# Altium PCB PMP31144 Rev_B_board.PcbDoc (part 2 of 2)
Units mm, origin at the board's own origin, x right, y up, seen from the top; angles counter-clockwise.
Board outline 104.14 x 73.15 mm, 4 copper layers (Top Layer, Layer 1, Layer 2, Bottom Layer), stack 1.787 mm thick; 110 components, 51 nets, 277 pads, 139 vias.
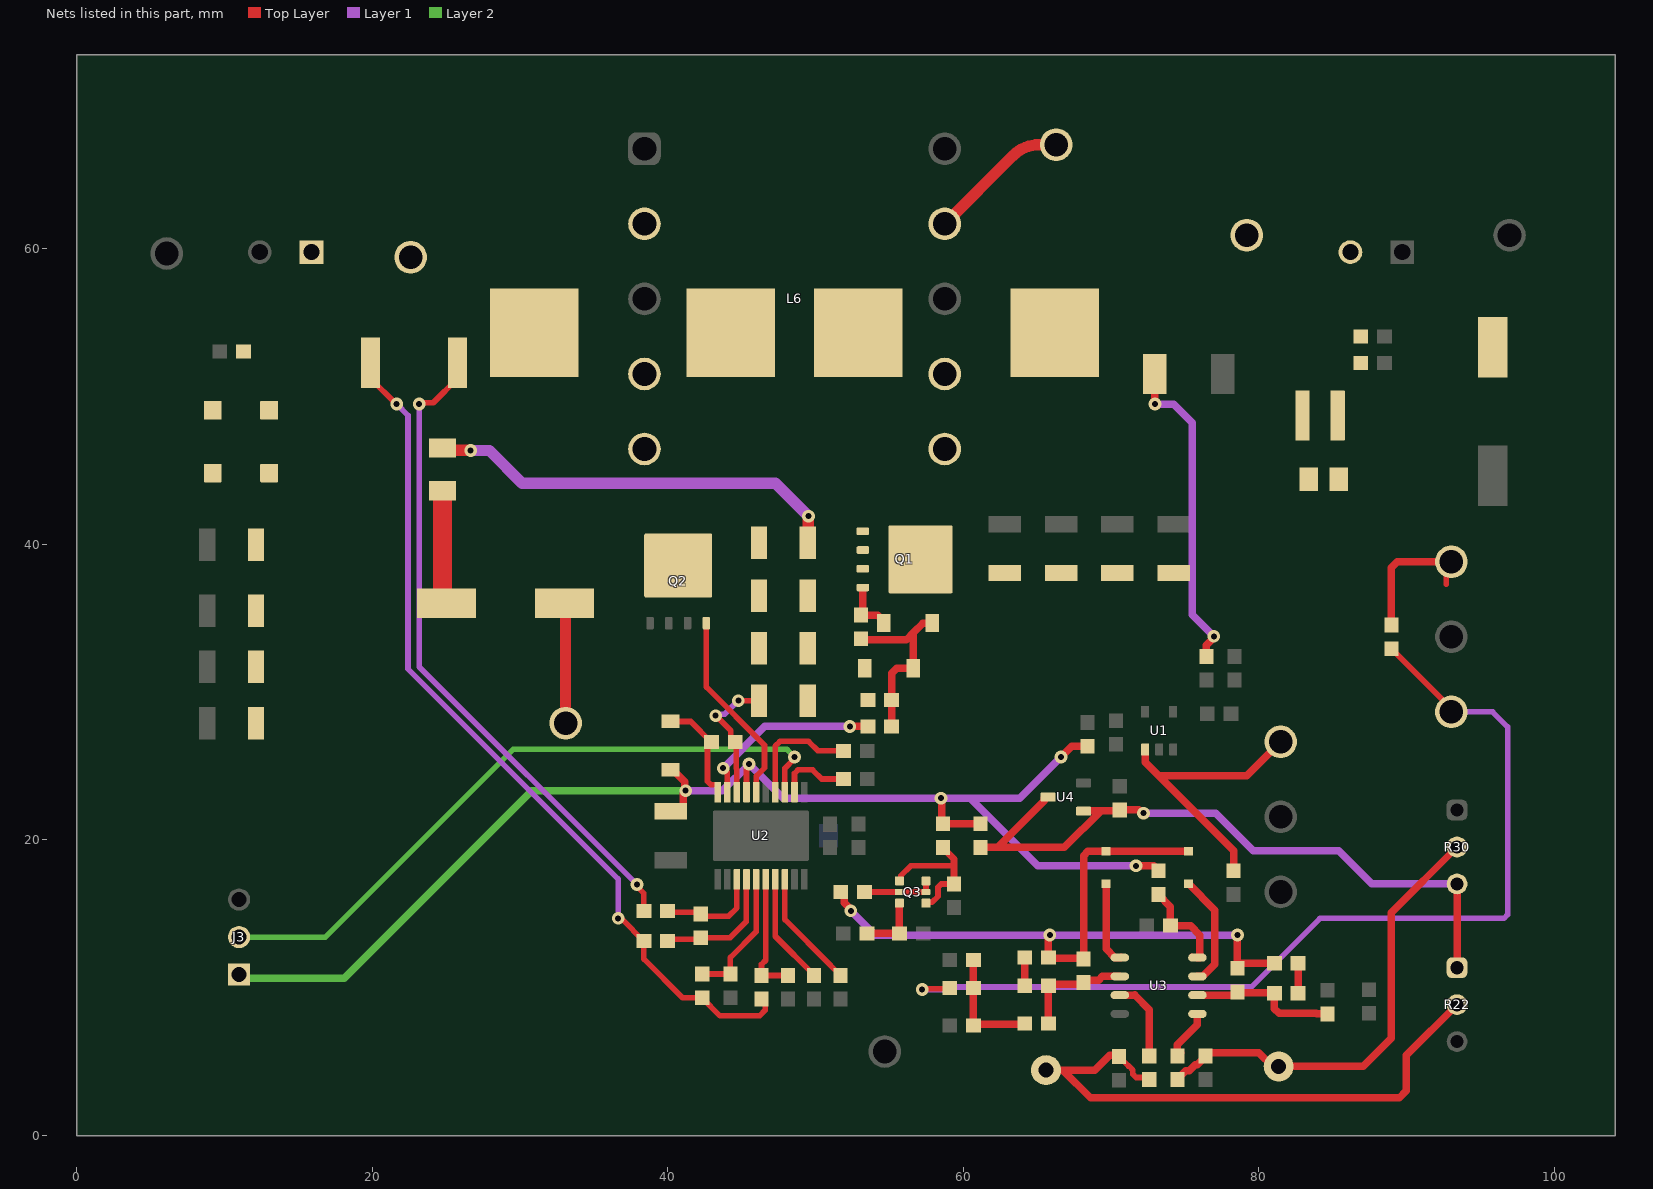
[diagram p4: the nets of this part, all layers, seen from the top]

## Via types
v1: diameter 0.864, hole 0.406, Top Layer to Bottom Layer, 59 vias
v2: diameter 1.016, hole 0.508, Top Layer to Bottom Layer, 39 vias
v3: diameter 1.016, hole 0.508, Top Layer to Bottom Layer, tented top, 15 vias
v4: diameter 0.864, hole 0.406, Top Layer to Bottom Layer, tented top, 11 vias
v5: diameter 0.5, hole 0.2, Top Layer to Bottom Layer, 9 vias
v6: diameter 0.5, hole 0.2, Top Layer to Bottom Layer, tented both sides, 6 vias

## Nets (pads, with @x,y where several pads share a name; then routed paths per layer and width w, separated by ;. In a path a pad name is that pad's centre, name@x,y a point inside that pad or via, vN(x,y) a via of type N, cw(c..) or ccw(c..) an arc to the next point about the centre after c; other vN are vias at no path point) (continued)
NetC3_1: C3.1 C4.1 C5.1 C6.1 D1.2 L1.2 L6.6 L6.9 Q1.1 Q1.2 Q1.3 R6.2 R11.1 TP5.1 | length 38.5
  Top Layer w0.508: C3.1@49.477,29.431 C3.1@49.698,29.21
  Top Layer w0.762: R6.2@24.765,46.535 24.926,46.374 26.651,46.374 v1(26.67,46.355) ; C6.1@49.477,40.099 49.511,40.133 49.511,41.891 v1(49.53,41.91) ; L6.9@58.75,61.697 63.366,66.312 cw(c65.162,64.516) 65.162,67.056 TP5.1@66.294,67.056
  Layer 1 w0.762: v1(26.67,46.355) 27.94,46.355 30.153,44.142 47.298,44.142 v1(49.53,41.91)
NetC3_2: C3.2 C4.2 C5.2 C6.2 C7.1 C21.1 L2.2 L6.4 L6.5 Q2.5 Q2.6 Q2.7 Q2.8 Q2.9@40.715,38.575 TP7.1 U2.18 | length 17.3
  Top Layer w0.381: v1(43.255,28.415) 44.271,27.399 44.271,26.922 44.555,26.637 C21.1@44.571,26.637 44.632,26.576 44.632,24.84 44.686,24.786 U2.18@44.686,23.237 ; v1(44.779,29.431) C3.2@46.177,29.431
  Top Layer w0.762: C7.1@33.031,36.035 33.095,35.971 TP7.1@33.095,27.907
  Layer 1 w0.381: v1(43.255,28.415) 43.347,28.507 43.855,28.507 v1(44.779,29.431)
NetC7_2: C7.2 R6.1 | length 7.7
  Top Layer w1.27: R6.1@24.765,43.635 24.765,36.301 C7.2@25.031,36.035
NetC8_1: C8.1 C9.1 C10.1 C11.1 L4.1 Q1.5 Q1.6 Q1.7 Q1.8 Q1.9@57.113,38.989 R7.1
NetC12_1: C12.1 R9.1 U2.5 | length 9
  Top Layer w0.381: R9.1@42.341,10.927 C12.1@44.246,10.927 44.246,12.05 45.986,13.79 U2.5@45.986,17.337
NetC13_1: C13.1 R13.1 U2.4 | length 8.5
  Top Layer w0.381: R13.1@39.991,13.175 40.099,13.283 42.131,13.283 C13.1@42.239,13.391 44.233,13.391 45.321,14.479 U2.4@45.321,17.077
NetC13_2: C13.2 R14.1 U2.3 | length 7
  Top Layer w0.381: R14.1@39.991,15.207 40.099,15.099 42.131,15.099 C13.2@42.239,14.991 42.391,14.839 44.126,14.839 44.686,15.399 U2.3@44.686,17.337
NetC14_1: C14.1 J1.1 L3.1 L5.1 TP4.1
NetC15_1: C15.1 C37.1 C38.1 J2.2 L4.2 R7.2 R10.1 TP6.1 TP15.1 | length 9.8
  Top Layer w0.381: 92.689,37.31 92.689,38.479 TP6.1@93.039,38.829
  Top Layer w0.508: R10.1@88.975,34.549 88.975,38.429 89.375,38.829 TP6.1@93.039,38.829
NetC16_1: C16.1 C17.1 C18.1 C19.1 L3.2 L5.2 R8.2 R9.2 R12.2 R13.2 | length 58.9
  Top Layer w0.381: R8.2@19.887,52.291 19.887,51.241 21.631,49.497 v1(21.665,49.497) ; v1(36.651,14.699) 36.743,14.607 36.934,14.607 38.366,13.175 R13.2@38.391,13.175 38.391,11.943 41.007,9.327 R9.2@42.341,9.327 42.341,9.302 43.548,8.095 46.221,8.095 46.609,8.483 R12.2@46.609,9.233
  Layer 1 w0.381: v1(21.665,49.497) 22.427,48.735 22.427,31.581 36.651,17.357 v1(36.651,14.699)
NetC20_1: C20.1 D1.1 D100.1 R11.2 R100.1 | length 12.9
  Top Layer w0.5: R100.1@53.086,33.617 53.146,33.557 56.163,33.557 56.628,34.022 ; C20.1@55.156,27.686 R11.2@55.156,29.464 55.156,31.28 55.499,31.623 D1.1@56.628,31.623 56.628,34.022 ; D100.1@57.898,34.671 57.277,34.671 56.628,34.022
NetC20_2: C20.2 U2.19 | length 12.7
  Top Layer w0.381: v4(43.756,24.859) 43.763,24.859 44.036,24.586 U2.19@44.036,23.237
  Top Layer w0.5: v4(52.324,27.686) C20.2@53.556,27.686
  Layer 1 w0.5: v4(43.756,24.859) 46.583,27.686 v4(52.324,27.686)
  Layer 2 w0.381: v4(43.756,24.859) v4@43.763,24.859
NetC21_2: C21.2 D2.1 U2.20 | length 7.4
  Top Layer w0.381: D2.1@40.207,28.021 41.562,28.021 42.946,26.637 C21.2@42.971,26.637 42.696,26.362 42.696,23.97 42.92,23.747 43.351,23.747 43.386,23.712 U2.20@43.386,23.237
NetC22_1: C22.1 U2.7 | length 7.6
  Top Layer w0.381: U2.7@47.286,17.337 47.286,13.483 49.911,10.858 C22.1@49.911,10.833 ; C22.1@50.165,10.833 C22.1@50.165,10.858
NetC23_1: C23.1 U2.14 | length 8.1
  Top Layer w0.381: U2.14@47.286,23.237 47.286,26.35 47.606,26.67 49.53,26.67 50.165,26.035 C23.1@51.905,26.035
NetC25_1: C25.1 R20.1 R21.2 U3.2 | length 7.6
  Top Layer w0.508: R21.2@65.772,7.595 R20.1@65.772,10.135 65.88,10.243 68.039,10.243 C25.1@68.147,10.351 68.312,10.516 69.163,10.516 69.417,10.77 U3.2@70.602,10.77
NetC25_2: C25.2 C26.1 C31.2 C32.1 D3.2 D4.2 R26.1 | length 51.3
  Top Layer w0.508: R26.1@51.719,16.477 51.744,16.477 51.965,16.256 51.965,15.737 52.399,15.303 v1(52.399,15.207) ; v1(65.861,13.564) 65.772,13.475 C26.1@65.772,12.04 65.817,11.996 68.102,11.996 C25.2@68.147,11.951 68.147,18.938 68.445,19.236 D3.2@69.671,19.236 D4.2@75.259,19.236 ; C31.2@78.561,11.316 78.561,11.341 78.879,11.659 C32.1@81.063,11.659 ; C31.2@78.561,11.532 v1(78.561,13.564)
  Layer 1 w0.508: v1(52.399,15.207) 54.042,13.564 v1(65.861,13.564) v1(78.561,13.564)
NetC26_2: C26.2 R20.2 | length 1.9
  Top Layer w0.508: R20.2@64.172,10.135 C26.2@64.172,12.04
NetC27_2: C27.2 R34.2 U3.8 | length 6.8
  Top Layer w0.381: U3.8@75.47,12.118 75.548,12.04 U3.8@75.852,12.04
  Top Layer w0.508: R34.2@73.227,16.32 73.227,16.295 74.027,15.495 C27.2@74.027,14.199 75.386,14.199 76.021,13.564 76.021,12.059 76.002,12.04 U3.8@75.852,12.04
NetC29_1: C29.1 R22.2 R23.1 TP12.1 | length 39.8
  Top Layer w0.381: C29.1@70.56,5.347 70.56,5.322 71.181,4.701 71.21,4.701 71.479,4.431 71.479,4.153 71.703,3.929 72.448,3.929 R23.1@72.592,3.785
  Top Layer w0.508: TP12.1@65.607,4.42 66.742,4.42 ; C29.1@70.56,5.322 70.446,5.436 69.925,5.436 68.909,4.42 66.742,4.42 ; R23.1@72.592,3.785 R23.1@72.592,3.81 ; R22.2@93.42,8.857 89.991,5.428 89.991,3.015 89.516,2.54 68.622,2.54 66.742,4.42
NetC31_1: C31.1 R28.1 R29.2 U3.6 | length 10.5
  Top Layer w0.508: U3.6@76.213,9.5 U3.6@75.852,9.5 75.86,9.508 78.353,9.508 C31.1@78.561,9.716 78.605,9.672 81.018,9.672 R28.1@81.063,9.627 81.063,8.59 81.38,8.273 83.889,8.273 83.932,8.23 R29.2@84.657,8.23
NetC32_2: C32.2 R28.2 | length 2
  Top Layer w0.508: R28.2@82.663,9.627 C32.2@82.663,11.659
NetC34_1: C34.1 R30.2 R31.1 TP14.1 | length 30.9
  Top Layer w0.508: R31.1@74.497,3.785 74.497,3.81 75.064,4.377 75.301,4.377 75.717,4.793 75.835,4.793 76.402,5.36 C34.1@76.402,5.385 ; C34.1@76.623,5.606 80.011,5.606 80.943,4.674 TP14.1@81.355,4.674 87.078,4.674 88.975,6.571 88.975,15.08 R30.2@93.42,19.525
NetC36_2: C36.2 Q3.1 Q3.4 R33.1 | length 9.8
  Top Layer w0.381: Q3.1@55.683,17.227 55.792,17.337 55.792,17.584 56.463,18.255 59.377,18.255 ; Q3.4@57.483,15.727 57.554,15.798 57.863,15.798 57.897,15.833 57.938,15.833 58.292,16.186 58.292,16.8 58.515,17.023 C36.2@59.377,17.023
  Top Layer w0.457: R33.1@58.622,19.495 58.622,19.47 59.377,18.715 59.377,18.255 C36.2@59.377,17.023
NetD3_1: D3.1 U3.1 | length 5.7
  Top Layer w0.508: D3.1@69.671,17.036 69.671,12.632 70.263,12.04 U3.1@70.602,12.04 70.668,12.04 U3.1@70.687,12.059
NetD4_1: D4.1 U3.7 | length 7.7
  Top Layer w0.508: D4.1@75.259,17.036 77.037,15.258 77.037,11.605 76.202,10.77 U3.7@75.852,10.77
NetD100_2: D100.2 Q1.4 R100.2 | length 3.8
  Top Layer w0.5: Q1.4@53.213,37.084 53.213,35.344 R100.2@53.086,35.217 54.23,35.217 54.624,34.824 D100.2@54.624,34.671
NetJ3_2: J3.2 U2.13 | length 45.7
  Top Layer w0.381: U2.13@47.936,23.237 47.936,24.855 48.589,25.508 v4(48.589,25.621)
  Layer 2 w0.381: J3.2@10.997,13.429 16.839,13.429 29.539,26.129 48.081,26.129 v4(48.589,25.621)
NetL1_1: L1.1 L6.7 R2.1 R5.2 | length 21.7
  Top Layer w0.508: R5.2@72.959,51.529 72.973,51.515 v1(72.973,49.497) ; R2.1@76.454,32.423 76.455,33.179 76.962,33.686 v1(76.962,33.782)
  Layer 1 w0.508: v1(72.973,49.497) 74.243,49.497 75.513,48.227 75.513,35.231 v1(76.962,33.782)
NetL2_1: L2.1 L6.2 R8.1 R14.2 | length 45
  Top Layer w0.381: v1(23.189,49.497) 23.281,49.589 24.135,49.589 25.787,51.241 R8.1@25.787,52.291 ; v1(37.921,16.985) 37.921,16.854 38.391,16.384 R14.2@38.391,15.207
  Layer 1 w0.381: v1(23.189,49.497) 23.189,31.717 v1(37.921,16.985)
NetQ2_4: Q2.4 U2.16 | length 13.3
  Top Layer w0.381: Q2.4@42.62,34.675 42.62,30.351 46.557,26.414 46.557,24.884 46.005,24.333 U2.16@46.005,23.237
NetQ3_2: Q3.2 Q3.5 Q3.6 R26.2 | length 4.9
  Top Layer w0.381: R26.2@53.319,16.477 Q3.2@55.683,16.477 Q3.5@57.483,16.477 Q3.6@57.483,17.227
NetQ3_3: Q3.3 R24.1 R25.2 | length 4.3
  Top Layer w0.508: R24.1@53.486,13.683 R25.2@55.696,13.683 55.689,13.69 55.689,15.72 Q3.3@55.683,15.727
NetR3_2: R3.2 TP1.1 U1.1 | length 19.9
  Top Layer w0.508: U1.1@72.31,26.124 72.331,26.103 72.331,25.247 73.227,24.351 ; R3.2@78.307,17.92 78.307,19.271 73.227,24.351 ; TP1.1@81.482,26.645 79.188,24.351 73.227,24.351
NetR10_2: R10.2 R15.2 TP10.1 | length 66.8
  Top Layer w0.381: v1(57.225,9.873) 57.276,9.924 59.041,9.924 R15.2@59.092,9.975 ; R10.2@88.975,32.949 88.975,32.924 89.259,32.64 89.285,32.64 93.039,28.885 TP10.1@93.039,28.669
  Top Layer w0.508: R15.2@58.94,10.127 R15.2@59.092,9.975
  Layer 1 w0.381: v1(57.225,9.873) 58.84,9.873 59.017,10.05 79.5,10.05 84.149,14.699 96.595,14.699 96.849,14.953 96.849,27.653 95.833,28.669 TP10.1@93.039,28.669
NetR12_1: R12.1 R17.2 U2.6 | length 8.5
  Top Layer w0.381: R12.1@46.355,10.833 R12.1@46.609,10.833 ; U2.6@46.631,17.332 U2.6@46.636,17.337 46.636,11.864 46.355,11.583 46.355,11.087 R12.1@46.609,10.833 ; R12.1@46.636,10.833 R12.1@46.609,10.833 ; R17.2@48.133,10.833 R12.1@46.609,10.833
NetR18_2: R18.2 U2.12 | length 4.9
  Top Layer w0.381: U2.12@48.586,23.237 48.586,24.509 48.822,24.745 49.815,24.745 50.43,24.13 R18.2@51.905,24.13
NetR19_2: R19.2 U2.8 | length 8.1
  Top Layer w0.381: U2.8@47.936,17.337 47.936,14.617 50.996,11.557 50.996,11.551 51.689,10.858 R19.2@51.689,10.833
NetR23_2: R23.2 U3.3 | length 6.2
  Top Layer w0.508: U3.3@70.252,9.5 U3.3@70.602,9.5 70.61,9.508 71.6,9.508 71.602,9.51 72.592,8.52 R23.2@72.592,5.385 R23.2@72.371,5.606
NetR31_2: R31.2 U3.5 | length 3.7
  Top Layer w0.508: R31.2@74.718,5.606 R31.2@74.497,5.385 74.497,6.135 75.852,7.49 U3.5@75.852,8.23
VCC: C24.2 D2.2 J3.1 R1.2 R32.2 R33.2 R34.1 U2.17 | length 91.2
  Top Layer w0.381: U2.17@45.336,23.237 45.336,24.835 45.508,25.007 v4(45.508,25.137)
  Top Layer w0.508: C24.2@40.207,21.937 40.757,21.937 41.053,22.233 41.053,23.165 v1(41.223,23.335) 41.155,23.403 41.155,23.95 40.36,24.746 D2.2@40.207,24.746 ; v1(58.495,22.827) 58.558,22.764 58.558,21.158 R33.2@58.622,21.095 R32.2@61.162,21.095 ; v1(66.623,25.621) 67.347,26.345 R1.2@68.401,26.345 ; v1(71.703,18.255) 71.708,18.25 72.897,18.25 72.981,18.166 73.006,18.166 73.227,17.945 R34.1@73.227,17.92
  Layer 1 w0.508: v1(41.223,23.335) 43.706,23.335 v4(45.508,25.137) 47.819,22.827 v1(58.495,22.827) 60.483,22.827 ; v1(66.623,25.621) 63.829,22.827 60.483,22.827 ; v1(71.703,18.255) 65.055,18.255 60.483,22.827
  Layer 2 w0.508: J3.1@10.997,10.889 11.251,10.635 18.109,10.635 30.809,23.335 v1(41.223,23.335) ; v4@45.508,25.041 v4(45.508,25.137)
"Voltage Loop": C28.1 R15.1 R16.2 R21.1 | length 8
  Top Layer w0.508: R16.2@60.692,11.88 R15.1@60.692,9.975 C28.1@60.692,7.435 60.772,7.515 64.092,7.515 R21.1@64.172,7.595
VREF: C35.1 R22.1 R30.3 R32.1 U4.1 U4.3 | length 47.2
  Top Layer w0.508: R32.1@61.162,19.495 62.341,19.495 ; U4.3@65.747,22.901 65.547,22.901 65.501,22.855 65.501,22.655 62.341,19.495 ; U4.1@68.147,21.951 68.189,21.993 69.345,21.993 ; v4(72.211,21.811) 72.115,21.811 71.891,22.035 C35.1@70.597,22.035 70.555,21.993 69.345,21.993 ; R22.1@93.42,11.357 R30.3@93.42,17.025 ; 62.341,19.495 66.847,19.495 69.345,21.993
  Layer 1 w0.508: v4(72.211,21.811) 77.085,21.811 79.625,19.271 85.419,19.271 87.665,17.025 R30.3@93.42,17.025
pads on no net: L6.1 L6.3 L6.8 L6.10 Q1.9@55.853,37.519 Q1.9@55.853,38.989 Q1.9@55.853,40.459 Q1.9@57.533,37.519 Q1.9@57.533,38.989 Q1.9@57.533,40.459 Q2.9@39.245,37.315 Q2.9@39.245,38.995 Q2.9@40.715,37.315 Q2.9@40.715,38.995 Q2.9@42.185,37.315 Q2.9@42.185,38.995 U2.1 U2.21@46.311,20.287

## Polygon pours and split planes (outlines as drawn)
NetC3_2 on Top Layer "TOP_LAYER_NETC3_2_P026" (solid, remove dead copper, pour order 26): 47.64,29.411 47.64,28.577 cw(c47.242,28.577) 47.523,28.296 cw(c46.91,28.909) 46.91,28.042 45.794,28.042 cw(c45.794,28.649) 45.364,28.219 44.192,29.392 cw(c45.103,30.302) 43.815,30.302 43.815,35.281 ccw(c43.14,35.281) 43.617,35.758 43.497,35.877 ccw(c42.731,35.111) 42.731,36.195 37.752,36.195 ccw(c37.752,35.501) 37.262,35.992 35.829,34.559 cw(c35.179,35.21) 35.179,34.29 30.875,34.29 cw(c30.875,35.244) 30.201,34.569 29.418,35.352 cw(c29.982,35.916) 29.185,35.916 29.185,46.538 cw(c30.399,46.538) 29.54,47.396 30.654,48.51 cw(c31.521,47.643) 31.521,48.87 34.415,48.87 ccw(c34.415,50.04) 35.242,49.212 ccw(c34.537,49.918) 35.535,49.918 35.535,57.061 cw(c36.055,57.061) 35.687,57.429 35.935,57.677 cw(c36.195,57.417) 36.195,57.785 47.176,57.785 cw(c47.176,56.701) 47.942,57.468 cw(c47.176,56.701) 48.26,56.701 48.26,44.264 cw(c47.176,44.264) 47.942,43.497 ccw(c48.709,42.731) 47.625,42.731 47.625,42.291
NetC3_1 on Top Layer "Top Layer-NetC3_1" (solid, remove dead copper, pour order 25): 60.947,58.991 61.582,59.627 61.582,59.937 ccw(c60.467,60.106) 61.595,60.106 61.595,62.484 ccw(c60.675,62.484) 61.326,63.134 61.087,63.373 ccw(c60.167,62.453) 60.167,63.754 53.249,63.754 ccw(c53.249,61.214) 51.453,63.01 50.274,61.831 ccw(c52.07,60.035) 49.53,60.035 49.53,58.944 49.517,58.928 49.517,44.577 cw(c47.562,44.561) 48.955,43.19 48.882,43.116 ccw(c50.415,41.584) 48.247,41.583 48.247,29.045 ccw(c48.971,29.045) 48.971,28.321 50.091,28.321 50.088,28.323 ccw(c50.035,28.893) 50.439,28.488 50.599,28.649 cw(c51.341,27.907) 51.342,28.956 53.975,28.956 ccw(c53.975,29.21) 54.229,29.21 54.229,32.004 ccw(c53.721,32.004) 53.721,32.512 52.959,32.512 cw(c52.959,33.401) 52.07,33.401 52.07,35.749 cw(c52.452,35.749) 52.182,36.02 ccw(c51.84,36.362) 52.324,36.362 52.324,37.719 cw(c52.578,37.719) 52.578,37.973 53.467,37.973 ccw(c53.467,38.481) 53.975,38.481 53.975,41.021 cw(c54.61,41.021) 54.61,41.656 59.055,41.656 ccw(c59.055,42.913) 60.312,42.913 60.312,47.371 ccw(c59.493,47.378) 59.499,48.196 56.515,48.197 cw(c56.515,48.831) 55.88,48.831 55.867,49.403 55.867,57.277 55.88,57.339 cw(c56.833,57.339) 56.159,58.014 56.731,58.585 cw(c57.777,57.447) 57.498,58.968 59.395,58.991
AGND on Top Layer "TOP_LAYER_AGND_P004" (solid, remove dead copper, pour order 4): 50.011,18.001 51.002,18.992 51.002,22.023 49.605,23.368 49.605,27.145 52.907,30.447 97.865,30.447 97.865,1.999 41.616,1.999 41.616,18.001
GND on Top Layer "TOP_LAYER_GND_P020" (solid, pour order 20): 36.322,21.082 41.656,21.082 41.656,21.336 42.291,21.971 50.164,21.971 50.167,18.542 41.91,18.542 40.64,17.272 36.322,17.272 35.814,17.78 35.814,20.828
NetC15_1 on Top Layer "TOP_LAYER_NETC15_1_P017" (solid, pour order 17): 76.2,58.42 77.47,57.15 83.185,57.15 84.836,55.499 84.836,37.084 86.36,35.56 101.6,35.56 102.235,36.195 102.235,62.865 100.965,64.135 77.47,64.135 76.2,62.865
GND on Top Layer "TOP_LAYER_GND_P016" (solid, pour order 16): 92.964,46.99 93.218,47.244 98.298,47.244 98.806,46.736 98.806,42.164 98.552,41.91 93.218,41.91 92.964,42.164
GND on Top Layer "TOP_LAYER_GND_P015" (solid, pour order 15): 75.565,55.88 75.565,48.895 78.74,48.895 81.915,52.07 81.915,55.88
GND on Top Layer "TOP_LAYER_GND_P014" (solid, pour order 14): 60.579,43.307 61.468,44.196 61.468,45.212 61.722,45.466 75.692,45.466 76.2,44.958 76.2,41.656 75.311,40.767 60.579,40.767
NetC8_1 on Top Layer "TOP_LAYER_NETC8_1_P013" (solid, pour order 13): 79.375,48.895 81.28,50.8 83.566,50.8 84.074,50.292 84.074,36.449 82.169,34.544 76.581,34.544 76.2,34.163 76.2,33.782 75.438,33.02 54.864,33.02 54.864,40.259 77.724,40.259 79.375,41.91
NetL1_1 on Top Layer "TOP_LAYER_NETL1_1_P012" (solid, pour order 12): 72.39,46.355 74.295,48.26 74.295,59.69 73.025,60.96 64.135,60.96 62.23,59.055 62.23,54.61 60.96,53.34 57.785,53.34 56.515,52.07 56.515,48.895 61.595,48.895 64.135,46.355
GND on Top Layer "TOP_LAYER_GND_P011" (solid, pour order 11): 36.83,34.29 38.1,35.56 41.91,35.56 41.91,31.115 41.275,30.48 37.465,30.48 36.83,31.115
NetL2_1 on Top Layer "TOP_LAYER_NETL2_1_P009" (solid, pour order 9): 34.29,49.53 34.925,50.165 34.925,57.785 36.195,59.055 40.64,59.055 40.64,63.5 40.005,64.135 29.845,64.135 26.035,60.325 26.035,57.15 24.765,55.88 24.765,49.53
NetC16_1 on Top Layer "TOP_LAYER_NETC16_1_P007" (solid, pour order 7): 8.255,46.355 14.605,46.355 15.875,47.625 15.875,53.34 17.78,55.245 22.225,55.245 22.86,54.61 22.837,54.587 22.837,50.616 22.676,50.616 22.225,50.165 22.225,27.94 19.05,24.765 12.065,24.765 10.795,26.035 10.795,41.275 8.255,43.815
GND on Top Layer "TOP_LAYER_GND_P006" (solid, pour order 6): 8.89,25.4 9.525,26.035 9.525,41.275 8.255,42.545 5.08,42.545 4.445,41.91 4.445,27.305 6.35,25.4
NetC14_1 on Top Layer "TOP_LAYER_NETC14_1_P005" (solid, pour order 5): 3.175,70.485 23.495,70.485 25.4,68.58 25.4,57.15 24.13,55.88 16.51,55.88 14.605,53.975 14.605,48.26 13.97,47.625 4.445,47.625 3.175,48.895
GND on Layer 2 "LAYER_2_GND_P018" (solid, pour order 18): 86.36,31.75 91.186,36.576 102.235,36.576 102.235,69.215 100.33,71.12 4.445,71.12 1.905,68.58 1.905,6.35 3.81,4.445 17.145,4.445 19.05,6.35 19.05,19.685 27.305,27.94 48.895,27.94 52.705,31.75
AGND on Layer 2 "LAYER_2_AGND_P000" (solid, pour order 0): 87.376,30.447 92.362,35.433 97.865,35.433 97.865,1.999 35.635,1.999 35.635,23.843 36.397,24.605 49.605,24.605 49.605,27.145 52.907,30.447
GND on Bottom Layer "BOTTOM_LAYER_GND_P019" (solid, pour order 19): 4.445,71.12 1.905,68.58 1.905,3.175 3.175,1.905 101.6,1.905 102.235,2.54 102.235,69.215 100.33,71.12

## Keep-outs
Keep-Out Layer:
  text ".Layer_Name" at 14.656,-21.806 h1.52

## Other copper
Top Layer:
  text ".Layer_Name" at 14.656,-21.806 h1.52
Bottom Layer:
  pour cut-out: 76.581,49.911 77.978,49.911 77.978,48.641 76.581,48.641
  region net AGND: 50.367,22.319 55.447,22.319 55.447,17.747 50.367,17.747
  text ".Layer_Name" at 14.656,-21.806 h1.52

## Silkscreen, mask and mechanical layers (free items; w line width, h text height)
Top Overlay:
  lines w0.254: 48.768,13.716 50.8,13.716 ; 49.268,15.24 50.038,15.24 50.546,15.748 ; 50.292,23.368 50.8,22.86 50.8,22.098 ; 53.086,22.098 53.086,22.352 53.34,22.606 54.356,22.606 ; 63.119,7.493 62.484,8.128 62.484,14.732 63.5,15.748 ; 63.754,20.447 63.754,15.367 67.183,15.367 67.183,20.447 ; 63.767,20.523 64.275,20.523 67.196,20.523 ; 77.395,5.588 79.248,5.588 80.01,6.35 82.804,6.35 83.185,5.969 ; 83.185,3.175 83.185,5.969 ; 83.312,2.921 83.693,2.54 90.043,2.54 90.265,2.54 90.678,2.953 90.678,5.842 90.17,6.35 83.566,6.35 83.185,5.969
  text "VOUT 12/24V" at 74.803,68.961 h1.52
  text "VIN 9-36V" at 15.748,68.834 h1.52
  text "SW2" at 68.578,67.181 h1
  text "VOUT" at 81.788,64.516 h1.52
  text "GND" at 89.154,64.516 h1.52
  text "GND" at 9.144,64.389 h1.52
  text "VIN" at 15.494,64.262 h1.52
  text "VOUT" at 96.135,37.334 h1
  text "AGND" at 96.266,32.385 h1
  text "NWA" at 96.389,27.047 h1
  text "SW1" at 27.811,25.398 h1
  text "Iout" at 97.028,20.574 h1.52
  text "AGND" at 83.947,19.939 h1
  text "adj" at 97.409,18.034 h1.52
  text "[" at 14.351,17.145 h3.05 r180
  text "DEM" at 15.621,15.748 h1.52
  text "[" at 14.351,13.208 h3.05 r180
  text "Forced" at 15.315,12.022 h1.52
  text "Vout" at 97.282,10.287 h1.52
  text "PWM" at 15.494,9.779 h1.52
  text "adj" at 97.409,7.747 h1.52
  text "'.PRJ_Number'.PCB_Rev" at 17.907,2.794 h2.75
  text "AGND" at 53.213,0.762 h1
  text ".Layer_Name" at 14.656,-21.806 h1.52
  text "GND" at 178.232,-57.887 h0.89 r90
Bottom Overlay:
  text ".Layer_Name" at 14.656,-21.806 h1.52
Top Paste:
  text ".Layer_Name" at 14.656,-21.806 h1.52
Bottom Paste:
  text ".Layer_Name" at 14.656,-21.806 h1.52
Top Solder:
  text ".Layer_Name" at 14.656,-21.806 h1.52
  text ".Layer_Name" at 14.656,-21.806 h1.52
Bottom Solder:
  text ".Layer_Name" at 14.656,-21.806 h1.52
Drill Guide:
  text ".Layer_Name" at 14.656,-21.806 h1.52
M1 Board Outline:
  lines w0.254: 0,0 0,73.152 104.14,73.152 104.14,0 31.432,0 0,0
  text ".Layer_Name" at 14.656,-21.806 h1.52
M2 Board Dimensions:
  rectangle: 0,-6.985 3.175,-3.81
  rectangle: 3.175,-10.16 12.7,-6.985
  lines w0.178: 0,-6.985 25.4,-6.985 ; 3.175,-10.16 3.175,-3.81 ; 6.35,-10.16 6.35,-3.81 ; 12.7,-10.16 12.7,-3.81 ; 19.05,-10.16 19.05,-3.81 ; 0,-10.16 25.4,-10.16 25.4,-3.81 0,-3.81 0,-10.16
  text ".Layer_Name" at 14.656,-21.806 h1.52
M3 3D STEP Top:
  text ".Layer_Name" at 14.656,-21.806 h1.52
M4 3D STEP Bottom:
  text ".Layer_Name" at 14.656,-21.806 h1.52
M5 Assembly Top:
  lines w0.254: -7.417,-23.626 160.223,-23.626 ; -7.417,-18.462 160.274,-18.462 ; -7.417,-13.297 -7.417,-28.791 94.31,-28.791 160.274,-28.791 160.274,-13.297 -7.404,-13.297 -7.404,-28.791 32.614,-28.791 ; 55.194,-28.791 55.194,-13.297 ; 87.376,-18.462 87.376,-13.297 ; 108.712,-18.462 108.712,-13.297 ; 124.511,-28.956 124.511,-23.804
  text "COMPONENTS MARKED 'DNP' SHOULD NOT BE POPULATED." at 29.299,-8.09 h1.52
  text "ASSEMBLY VARIANT:" at 29.286,-11.024 h1.52
  text ".VariantName" at 55.601,-11.024 h1.52
  text "PCB VIEWED FROM TOP SIDE" at -5.804,-16.654 h1.52
  text "BOARD #:" at 57.099,-16.654 h1.52
  text ".PRJ_Number" at 70.955,-16.654 h1.52
  text "REV:" at 92.405,-16.654 h1.52
  text ".PCB_Rev" at 99.809,-16.654 h1.52
  text "SVN REV:" at 113.69,-16.654 h1.52
  text ".VersionControl_RevNumber" at 126.543,-16.654 h1.52
  text "TID #:" at 57.099,-21.819 h1.52
  text ".TID" at 70.955,-21.819 h1.52
  text "PLOT NAME =" at -5.804,-27.034 h1.52
  text ".plot_File_Name" at 14.656,-27.034 h1.52
  text "GENERATED    :" at 57.15,-27.034 h1.52
  text ".Print_Date" at 79.235,-27.034 h1.52
  text ".Print_Time" at 97.752,-27.034 h1.52
  text "TEXAS INSTRUMENTS" at 129.87,-27.034 h1.52
M6 Assembly Bottom:
  lines w0.254: -7.429,-18.474 160.261,-18.474 ; -7.379,-23.639 160.261,-23.639 ; 28.334,-28.969 28.334,-23.817 ; 44.133,-18.474 44.133,-13.31 ; 65.468,-18.474 65.468,-13.31 ; 97.65,-28.804 97.65,-13.31 ; 120.231,-28.804 160.249,-28.804 160.249,-13.31 -7.429,-13.31 -7.429,-28.804 58.534,-28.804 160.261,-28.804 160.261,-13.31
  text "COMPONENTS MARKED 'DNP' SHOULD NOT BE POPULATED." at 154.991,-8.077 h1.52
  text ".VariantName" at 128.473,-11.024 h1.52
  text "ASSEMBLY VARIANT:" at 154.864,-11.024 h1.52
  text ".VersionControl_RevNumber" at 26.302,-16.667 h1.52
  text "SVN REV:" at 39.154,-16.667 h1.52
  text ".PCB_Rev" at 53.035,-16.667 h1.52
  text "REV:" at 60.439,-16.667 h1.52
  text ".PRJ_Number" at 81.89,-16.667 h1.52
  text "BOARD #:" at 95.745,-16.667 h1.52
  text "PCB VIEWED FROM BOTTOM SIDE" at 158.648,-16.667 h1.52
  text ".TID" at 81.89,-21.831 h1.52
  text "TID #:" at 95.745,-21.831 h1.52
  text "TEXAS INSTRUMENTS" at 22.974,-27.047 h1.52
  text ".Print_Time" at 55.093,-27.047 h1.52
  text ".Print_Date" at 73.609,-27.047 h1.52
  text "GENERATED    :" at 95.694,-27.047 h1.52
  text ".plot_File_Name" at 138.189,-27.047 h1.52
  text "PLOT NAME =" at 158.648,-27.047 h1.52
M9 Title Sheet:
  drawing of 57 lines, arcs and shapes, not listed
  text "1" at 18.792,204.127 h1.78
  text "2" at 82.182,204.127 h1.78
  text "3" at 145.411,204.127 h1.78
  text "4" at 209.08,204.127 h1.78
  text "5" at 272.555,204.127 h1.78
  text "6" at 336.182,204.127 h1.78
  text "A" at -10.579,175.095 h1.78
  text "A" at 365.341,175.095 h1.78
  text "B" at -10.579,114.643 h1.78
  text "B" at 365.341,114.643 h1.78
  text "C" at -10.579,54.318 h1.78
  text "C" at 365.341,54.318 h1.78
  text "PROJECT TITLE:" at 288.125,7.048 h1.14
  text ".PRJ_Title" at 289.395,3.662 h1.78
  text "DESIGNED FOR:" at 288.125,-0.597 h1.14
  text ".PRJ_Customer" at 289.395,-4.153 h1.78
  text "D" at -10.579,-5.88 h1.78
  text "D" at 365.341,-5.88 h1.78
  text "FILE NAME:" at 288.125,-8.217 h1.14
  text ".PCB_File_Name_No_Path" at 289.395,-11.265 h1.78
  text "Texas Instruments (TI) and/or its licensors do not warrant the accuracy or completeness of this specification" at 161.9,-15.376 h1.14
  text "ENGINEER:" at 288.125,-15.583 h1.14
  text "LAYOUT BY:" at 326.352,-15.583 h1.14
  text "or any information contained therein. TI and/or its licensors do not warrant that this design will meet" at 160.757,-18.237 h1.14
  text ".PRJ_Engineer" at 289.395,-19.52 h1.78
  text ".PCB_Layout" at 327.635,-19.52 h1.78
  text "the specifications, will be suitable for your application or fit for any particular purpose, or will operate in" at 160.757,-21.099 h1.14
  text ".Layer_Name" at 14.656,-21.806 h1.52
  text "ALTIUM DESIGNER VERSION:" at 326.352,-23.457 h1.14
  text "an implementation. TI and/or its licensors do not warrant that the design is production worthy. You should" at 160.757,-23.961 h1.14
  text "completely validate and test your design implementation to confirm the system functionality for your application." at 161.9,-26.822 h1.14
  text ".print_Scale" at 289.395,-26.843 h1.78
  text ".Application_BuildNumber" at 327.635,-26.843 h1.78
  text "1" at 18.792,-32.093 h1.78
  text "2" at 82.182,-32.093 h1.78
  text "3" at 145.411,-32.093 h1.78
  text "4" at 209.08,-32.093 h1.78
  text "5" at 272.555,-32.093 h1.78
  text "6" at 336.182,-32.093 h1.78
M10 Fab Notes:
  drawing of 189 lines, arcs and shapes, not listed
  text "DESIGN INFORMATION" at 314.503,161.447 h1.52
  text "MIN. TRACK WIDTH:" at 298.131,158.091 h1.52
  text "8" at 325.976,158.091 h1.52
  text "MIL" at 329.907,158.091 h1.52
  text "MIN. CLEARANCE:" at 298.131,154.938 h1.52
  text "0.2" at 324.452,154.938 h1.52
  text "mm" at 329.907,154.938 h1.52
  text "MIN. VIA PAD SIZE:" at 298.131,151.785 h1.52
  text "24" at 325.214,151.785 h1.52
  text "MIL" at 329.907,151.785 h1.52
  text "0.05mm (2MIL)" at 315.784,148.486 h1.52
  text "MINIMUM ANNULAR RING" at 289.769,148.277 h1.52
  text "EXTERNAL" at 333.768,148.277 h1.52
  text "PER" at 294.849,145.48 h1.52
  text "IPC-D-275 CLASS 2 LEVEL C" at 300.437,145.48 h1.52
  text "MIL, HOLES" at 338.238,142.928 h1.52
  text "+/-" at 328.27,142.709 h1.52
  text "+/-" at 349.961,142.709 h1.52
  text "REGISTRATION TOLERANCES:" at 289.769,142.682 h1.52
  text "METAL" at 320.243,142.682 h1.52
  text "5" at 334.879,142.683 h1.52
  text "3" at 356.037,142.683 h1.52
  text "MIL" at 358.99,142.682 h1.52
  text "HOLE SIZE TOLERANCE (UNLESS OTHERWISE SPECIFIED):" at 289.769,140.185 h1.52
  text "+/-" at 349.961,140.112 h1.52
  text "3" at 356.037,140.085 h1.52
  text "MIL" at 358.99,140.085 h1.52
  text "MATERIAL:" at 287.87,136.589 h1.52
  text "FR-4 High Tg" at 312.926,133.324 h1.52
  text "X" at 309.257,133.122 h1.52
  text "FR-408" at 298.563,133.007 h1.52
  text "OTHER" at 336.358,133.007 h1.52
  text "62 MIL (1.6mm) +/-10%" at 306.694,129.374 h1.52
  text "X" at 303.643,129.312 h1.52
  text "THICKNESS:" at 289.769,129.165 h1.52
  text "OTHER" at 339.33,129.165 h1.52
  text "TOLERANCE:" at 289.769,125.652 h1.52
  text "X" at 311.314,125.652 h1.52
  text "ANSI IPC-6012 TYPE 3 CLASS 2" at 315.836,125.652 h1.52
  text "OTHER +/-" at 315.835,121.989 h1.52
  text "BOW & TWIST:" at 289.769,118.302 h1.52
  text "X" at 311.314,118.302 h1.52
  text "ANSI IPC-6012 TYPE 3 CLASS 2" at 315.836,118.302 h1.52
  text "OTHER +/-" at 315.835,114.576 h1.52
  text "DRILLING:" at 287.87,111.258 h1.52
  text "NC_DRILL FILES" at 332.599,108.586 h1.52
  text "REFERENCE:" at 289.769,108.486 h1.52
  text "X" at 306.463,108.484 h1.52
  text "AS SHOWN" at 310.984,108.486 h1.52
  text "X" at 329.348,108.486 h1.52
  text "OTHER" at 340.168,104.873 h1.52
  text "PTH COPPER THICKNESS:" at 289.761,104.783 h1.52
  text "X" at 318.697,104.783 h1.52
  text "20-30 um" at 321.948,104.783 h1.52
  text "BOARD FINISH:" at 287.87,101.034 h1.52
  text "SILKSCREEN:" at 291.812,98.237 h1.52
  text "X" at 316.14,98.237 h1.52
  text "TOP" at 319.112,98.237 h1.52
  text "X" at 329.094,98.237 h1.52
  text "BOTTOM" at 332.091,98.237 h1.52
  text "SILKSCREEN COLOR:" at 291.812,94.295 h1.52
  text "X" at 316.115,94.295 h1.52
  text "WHITE" at 319.112,94.295 h1.52
  text "OTHER" at 332.091,94.295 h1.52
  text "X" at 319.442,90.652 h1.52
  text "GREEN" at 322.439,90.652 h1.52
  text "OTHER" at 338.136,90.652 h1.52
  text "SOLDER RESIST COLOR:" at 291.812,90.477 h1.52
  text "X" at 319.442,86.734 h1.52
  text "MATTE" at 322.439,86.734 h1.52
  text "SEMI-GLOSS" at 338.125,86.717 h1.52
  text "IMMERSION GOLD (ENIG)" at 314.819,82.345 h1.52
  text "ENEPIG" at 348.793,82.162 h1.52
  text "SURFACE FINISH:" at 287.87,82.136 h1.52
  text "X" at 310.298,82.136 h1.52
  text "IMM. TIN/SILVER OR EQUIV" at 296.24,78.649 h1.52
  text "OTHER" at 332.599,78.549 h1.52
  text "ARRAY/PANEL:" at 287.87,74.602 h1.52
  text "CUT AND TRIM PER M1 BOARD OUTLINE" at 314.819,74.393 h1.52
  text "N.C. ROUTE" at 314.819,70.94 h1.52
  text "X" at 332.295,70.94 h1.52
  text "V. SCORE" at 336.816,70.94 h1.52
  text "CERTIFICATION:" at 287.87,67.66 h1.52
  text "MATERIALS AND WORKMANSHIP FOR ALL PCBS" at 306.285,67.66 h1.52
  text "TO MEET OR EXCEED THE REQUIREMENTS OF:" at 306.285,65.271 h1.52
  text "X" at 297.078,62.003 h1.52
  text "ANSI IPC-A-600F CLASS ->" at 300.329,62.003 h1.52
  text "X" at 342.188,62.003 h1.52
  text "2" at 344.982,62.003 h1.52
  text "1" at 336.981,61.965 h1.52
  text "3" at 353.973,61.965 h1.52
  text "X" at 317.702,58.252 h1.52
  text "RoHS" at 320.953,58.252 h1.52
  text "OTHER" at 337.321,58.252 h1.52
  text "PER ORDER" at 347.407,58.252 h1.52
  text "ALL BOARDS MUST MEET OR EXCEED UL94-V0 REQUIREMENTS." at 288.569,54.345 h1.52
  text "PCB MUST BEAR THE UL94V-0 UL REGISTERED MATERIAL ID NUMBER" at 288.569,51.397 h1.52
  text "ADDITIONAL REQUIREMENTS:" at 287.87,47.094 h1.52
  text "MICROSECTION:" at 289.769,44.373 h1.52
  text "YES" at 312.775,44.373 h1.52
  text "REQUIRED" at 334.657,40.707 h1.52
  text "BARE BOARD ELEC. TEST:" at 289.769,40.634 h1.52
  text "NONE" at 322.935,40.634 h1.52
  text "X" at 331.66,40.634 h1.52
  text "PER ORDER" at 349.693,40.634 h1.52
  text "XX MIL VIAS REQUIRE NON-CONDUCTIVE FILL AND PLANARIZE" at 294.04,35.428 h1.5
  text "XX MIL VIAS REQUIRE CONDUCTIVE FILL AND PLANARIZE" at 294.243,32.787 h1.52
  text "OUTER XX MIL TRACES REQUIRE 50 OHM SINGLE-ENDED IMPEDANCE" at 294.218,28.637 h1.47
  text "LAYER 2 & 3 (INNER LAYERS) XX MIL WIDE, XX MIL SPACE / TRACES REQUIRE 100 OHM DIFFERENTIAL IMPEDANCE" at 294.015,22.65 h1.52
  text ".Layer_Name" at 14.656,-21.806 h1.52
M11 Gerber Information:
  lines w0.254: -7.417,-23.626 160.223,-23.626 ; -7.417,-18.462 160.274,-18.462 ; -7.417,-13.297 -7.417,-28.791 94.31,-28.791 160.274,-28.791 160.274,-13.297 -7.404,-13.297 -7.404,-28.791 32.614,-28.791 ; 55.194,-28.791 55.194,-13.297 ; 87.376,-18.462 87.376,-13.297 ; 108.712,-18.462 108.712,-13.297 ; 124.511,-28.956 124.511,-23.804
  text "ALL ARTWORK VIEWED FROM TOP SIDE" at -5.804,-16.654 h1.52
  text "BOARD #:" at 57.099,-16.654 h1.52
  text ".PRJ_Number" at 70.955,-16.654 h1.52
  text "REV:" at 92.405,-16.654 h1.52
  text ".PCB_Rev" at 99.809,-16.654 h1.52
  text "SVN REV:" at 113.69,-16.654 h1.52
  text ".VersionControl_RevNumber" at 126.543,-16.654 h1.52
  text "LAYER NAME =" at -5.804,-21.806 h1.52
  text "TID #:" at 57.099,-21.819 h1.52
  text ".TID" at 70.955,-21.819 h1.52
  text "PLOT NAME =" at -5.804,-27.034 h1.52
  text ".plot_File_Name" at 14.656,-27.034 h1.52
  text "GENERATED    :" at 57.15,-27.034 h1.52
  text ".Print_Date" at 79.235,-27.034 h1.52
  text ".Print_Time" at 97.752,-27.034 h1.52
  text "TEXAS INSTRUMENTS" at 129.87,-27.034 h1.52
M12 Stackup:
  drawing of 295 lines, arcs and shapes, not listed
  text "Layer" at 249.119,199.453 h1.52
  text "Name" at 259.531,199.453 h1.52
  text "Material" at 283.147,199.453 h1.52
  text "Thickness" at 304.985,199.453 h1.52
  text "Constant" at 321.49,199.453 h1.52
  text "Board Layer Stack" at 335.965,199.453 h1.52
  text "Top Overlay" at 259.531,196.405 h1.52
  text "Top Solder" at 259.531,193.357 h1.52
  text "Solder Resist" at 283.147,193.357 h1.52
  text "0.40mil" at 304.985,193.357 h1.52
  text "3.5" at 321.49,193.357 h1.52
  text "1" at 249.119,190.309 h1.52
  text "Top Layer" at 259.531,190.309 h1.52
  text "1.40mil" at 304.985,190.309 h1.52
  text "Dielectric 1" at 259.531,187.261 h1.52
  text "PP-006" at 283.147,187.261 h1.52
  text "2.80mil" at 304.985,187.261 h1.52
  text "4.1" at 321.49,187.261 h1.52
  text "2" at 249.119,184.213 h1.52
  text "Layer 1" at 259.531,184.213 h1.52
  text "CF-004" at 283.147,184.213 h1.52
  text "1.38mil" at 304.985,184.213 h1.52
  text "Dielectric1" at 259.531,181.165 h1.52
  text "FR-4" at 283.147,181.165 h1.52
  text "59.20mil" at 304.985,181.165 h1.52
  text "4.8" at 321.49,181.165 h1.52
  text "3" at 249.119,178.118 h1.52
  text "Layer 2" at 259.531,178.118 h1.52
  text "CF-004" at 283.147,178.118 h1.52
  text "1.38mil" at 304.985,178.118 h1.52
  text "Dielectric 2" at 259.531,175.07 h1.52
  text "PP-006" at 283.147,175.07 h1.52
  text "2.80mil" at 304.985,175.07 h1.52
  text "4.1" at 321.49,175.07 h1.52
  text "4" at 249.119,172.022 h1.52
  text "Bottom Layer" at 259.531,172.022 h1.52
  text "1.40mil" at 304.985,172.022 h1.52
  text "Bottom Solder" at 259.531,168.974 h1.52
  text "Solder Resist" at 283.147,168.974 h1.52
  text "0.40mil" at 304.985,168.974 h1.52
  text "3.5" at 321.49,168.974 h1.52
  text "Bottom Overlay" at 259.531,165.925 h1.52
  text ".Layer_Name" at 14.656,-21.806 h1.52
M13 Component Bodies Top:
  text ".Layer_Name" at 14.656,-21.806 h1.52
M14 Component Bodies Bottom:
  text ".Layer_Name" at 14.656,-21.806 h1.52
M15 Courtyards Top:
  text ".Layer_Name" at 14.656,-21.806 h1.52
M16 Courtyards Bottom:
  text ".Layer_Name" at 14.656,-21.806 h1.52
Drill Drawing:
  circle w0.254: c136.241,79.642 r0.703
  lines w0.254: 135.538,59.966 136.944,59.966 136.944,61.371 135.538,61.371 135.538,59.966 ; 135.538,63.831 136.241,63.128 136.944,63.831 136.241,64.533 135.538,63.831 ; 135.538,66.642 135.89,66.642 136.241,66.29 136.593,66.642 136.944,66.642 136.593,66.993 136.944,67.344 136.593,67.344 136.241,67.696 135.89,67.344 135.538,67.344 135.89,66.993 135.538,66.642 ; 135.538,70.858 136.944,70.858 136.241,69.452 135.538,70.858 ; 135.538,72.615 136.241,72.966 136.944,72.615 136.593,73.318 136.944,74.02 136.241,73.669 135.538,74.02 135.89,73.318 135.538,72.615 ; 135.538,75.777 135.538,76.128 135.89,76.48 135.538,76.831 135.538,77.183 135.89,77.183 136.241,76.831 136.593,77.183 136.944,77.183 136.944,76.831 136.593,76.48 136.944,76.128 136.944,75.777 136.593,75.777 136.241,76.128 135.89,75.777 135.538,75.777 ; 135.538,82.453 135.89,82.453 135.89,82.102 136.593,82.102 136.593,82.453 136.944,82.453 136.944,83.156 136.593,83.156 136.593,83.507 135.89,83.507 135.89,83.156 135.538,83.156 135.538,82.453
  lines w0.305: 134.264,59.017 216.362,59.017 ; 134.264,84.315 216.362,84.315 ; 142.85,55.855 142.85,87.478 ; 151.287,55.855 151.287,87.478 ; 167.453,55.855 167.453,87.478 ; 174.037,55.855 174.037,87.478 ; 183.568,55.855 183.568,87.478 ; 201.972,55.855 201.972,87.478 ; 134.264,55.855 216.362,55.855 216.362,87.478 134.264,87.478 134.264,55.855
  text "Symbol" at 136.162,85.264 h1.83
  text "Quantity" at 143.799,85.264 h1.83
  text "Finished Hole Size" at 152.235,85.264 h1.83
  text "Plated" at 168.402,85.264 h1.83
  text "Hole Type" at 174.986,85.264 h1.83
  text "Drill Layer Pair" at 184.517,85.264 h1.83
  text "Hole Tolerance" at 202.92,85.264 h1.83
  text "15" at 143.799,82.102 h1.52
  text "7.87mil (0.200mm)" at 152.235,82.102 h1.52
  text "PTH" at 168.402,82.102 h1.52
  text "Round" at 174.986,82.102 h1.52
  text "Top Layer - Bottom Layer" at 184.517,82.102 h1.52
  text "70" at 143.799,78.939 h1.52
  text "16.00mil (0.406mm)" at 152.235,78.939 h1.52
  text "PTH" at 168.402,78.939 h1.52
  text "Round" at 174.986,78.939 h1.52
  text "Top Layer - Bottom Layer" at 184.517,78.939 h1.52
  text "54" at 143.799,75.777 h1.52
  text "20.00mil (0.508mm)" at 152.235,75.777 h1.52
  text "PTH" at 168.402,75.777 h1.52
  text "Round" at 174.986,75.777 h1.52
  text "Top Layer - Bottom Layer" at 184.517,75.777 h1.52
  text "6" at 143.799,72.615 h1.52
  text "35.43mil (0.900mm)" at 152.235,72.615 h1.52
  text "PTH" at 168.402,72.615 h1.52
  text "Round" at 174.986,72.615 h1.52
  text "Top Layer - Bottom Layer" at 184.517,72.615 h1.52
  text "5" at 143.799,69.452 h1.52
  text "40.00mil (1.016mm)" at 152.235,69.452 h1.52
  text "PTH" at 168.402,69.452 h1.52
  text "Round" at 174.986,69.452 h1.52
  text "Top Layer - Bottom Layer" at 184.517,69.452 h1.52
  text "4" at 143.799,66.29 h1.52
  text "43.31mil (1.100mm)" at 152.235,66.29 h1.52
  text "PTH" at 168.402,66.29 h1.52
  text "Round" at 174.986,66.29 h1.52
  text "Top Layer - Bottom Layer" at 184.517,66.29 h1.52
  text "10" at 143.799,63.128 h1.52
  text "62.99mil (1.600mm)" at 152.235,63.128 h1.52
  text "PTH" at 168.402,63.128 h1.52
  text "Round" at 174.986,63.128 h1.52
  text "Top Layer - Bottom Layer" at 184.517,63.128 h1.52
  text "13" at 143.799,59.966 h1.52
  text "63.00mil (1.600mm)" at 152.235,59.966 h1.52
  text "PTH" at 168.402,59.966 h1.52
  text "Round" at 174.986,59.966 h1.52
  text "Top Layer - Bottom Layer" at 184.517,59.966 h1.52
  text "177 Total" at 143.799,56.803 h1.52
  text ".Layer_Name" at 14.656,-21.806 h1.52
M17 Embedded Cavity:
  text ".Layer_Name" at 14.656,-21.806 h1.52
M18 Embedded Assembly:
  text ".Layer_Name" at 14.656,-21.806 h1.52
M19 Embedded Keepout:
  text ".Layer_Name" at 14.656,-21.806 h1.52

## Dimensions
0,-10.16 to 25.4,-10.16 on M2 Board Dimensions
0,0 to 104.14,0 on M2 Board Dimensions
0,0 to 0,73.152 on M2 Board Dimensions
